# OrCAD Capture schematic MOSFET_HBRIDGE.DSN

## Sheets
1 PAGE2: size A
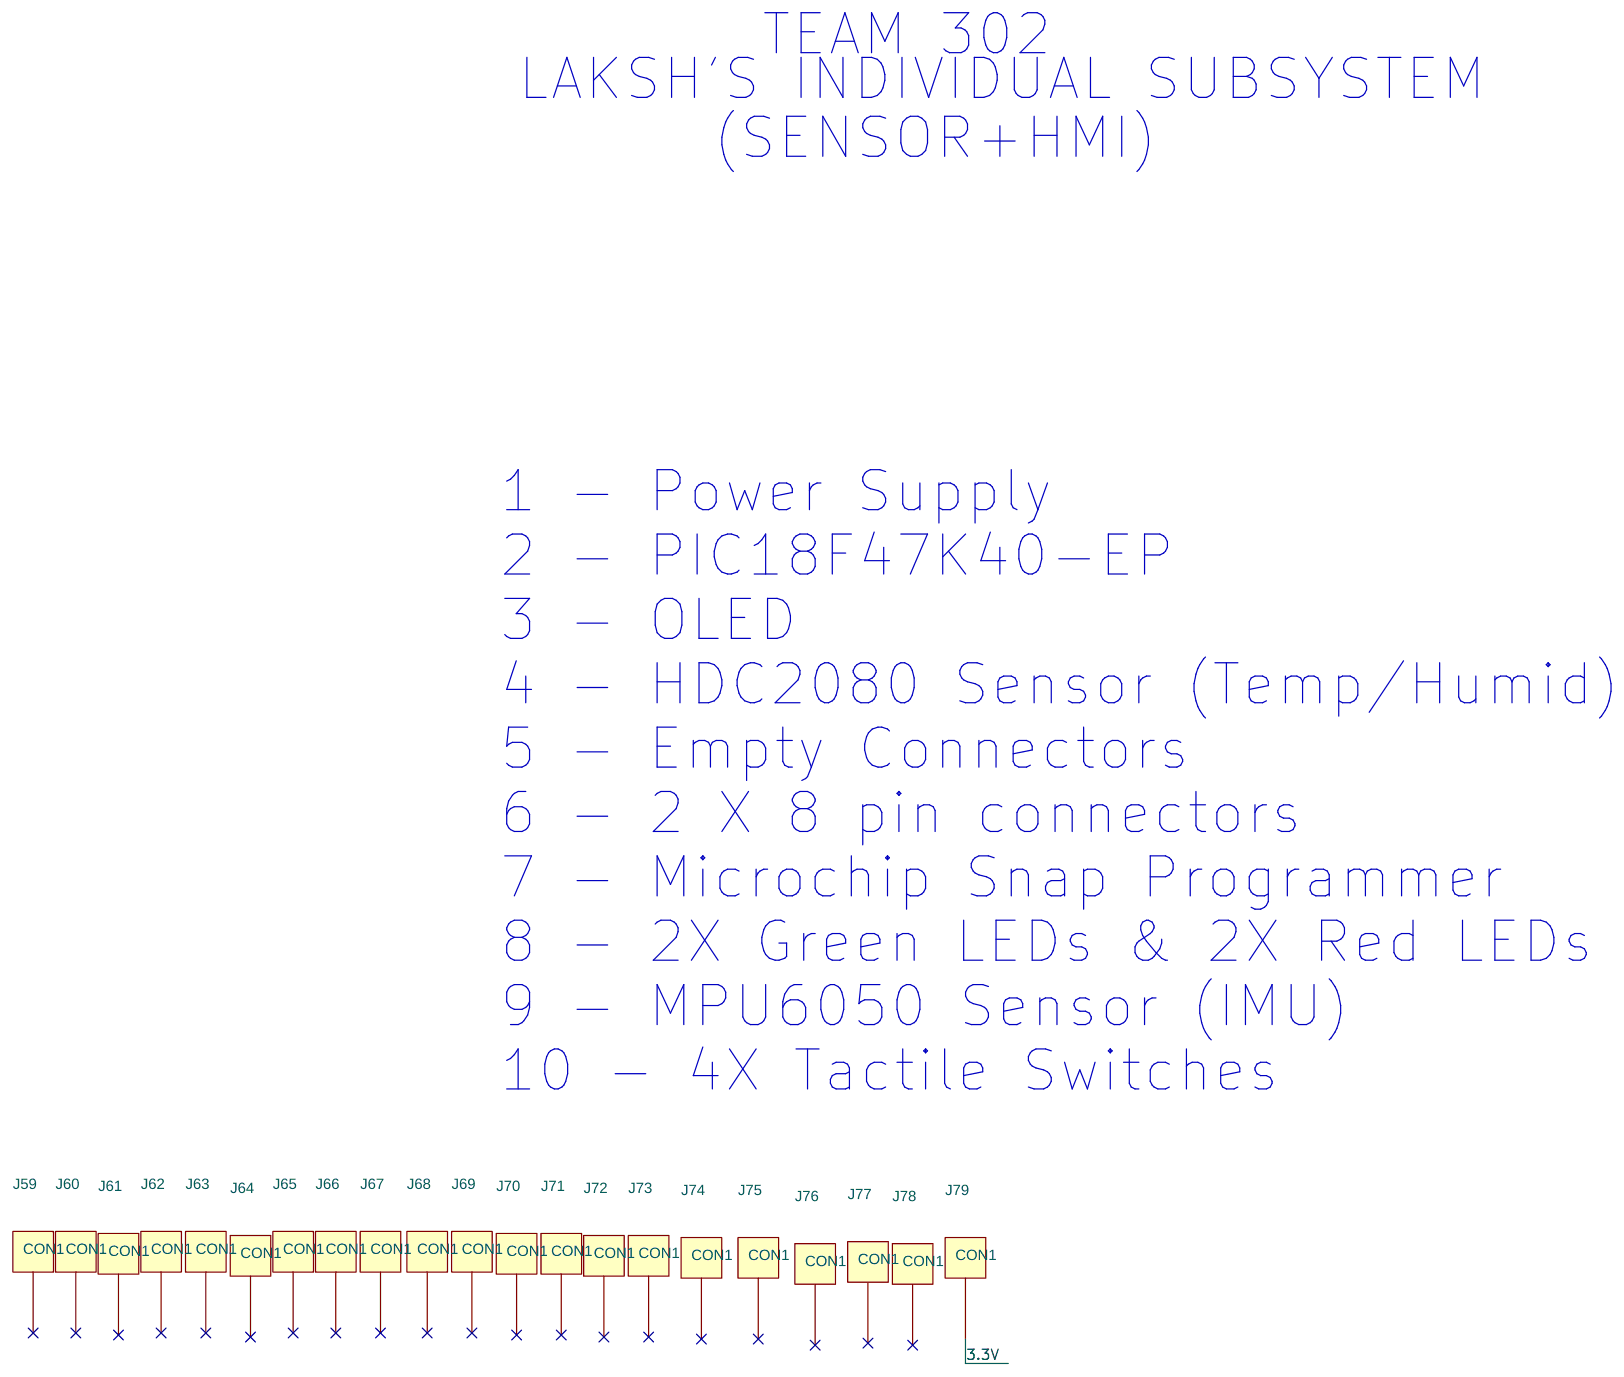
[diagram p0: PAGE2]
2 PAGE1: size A
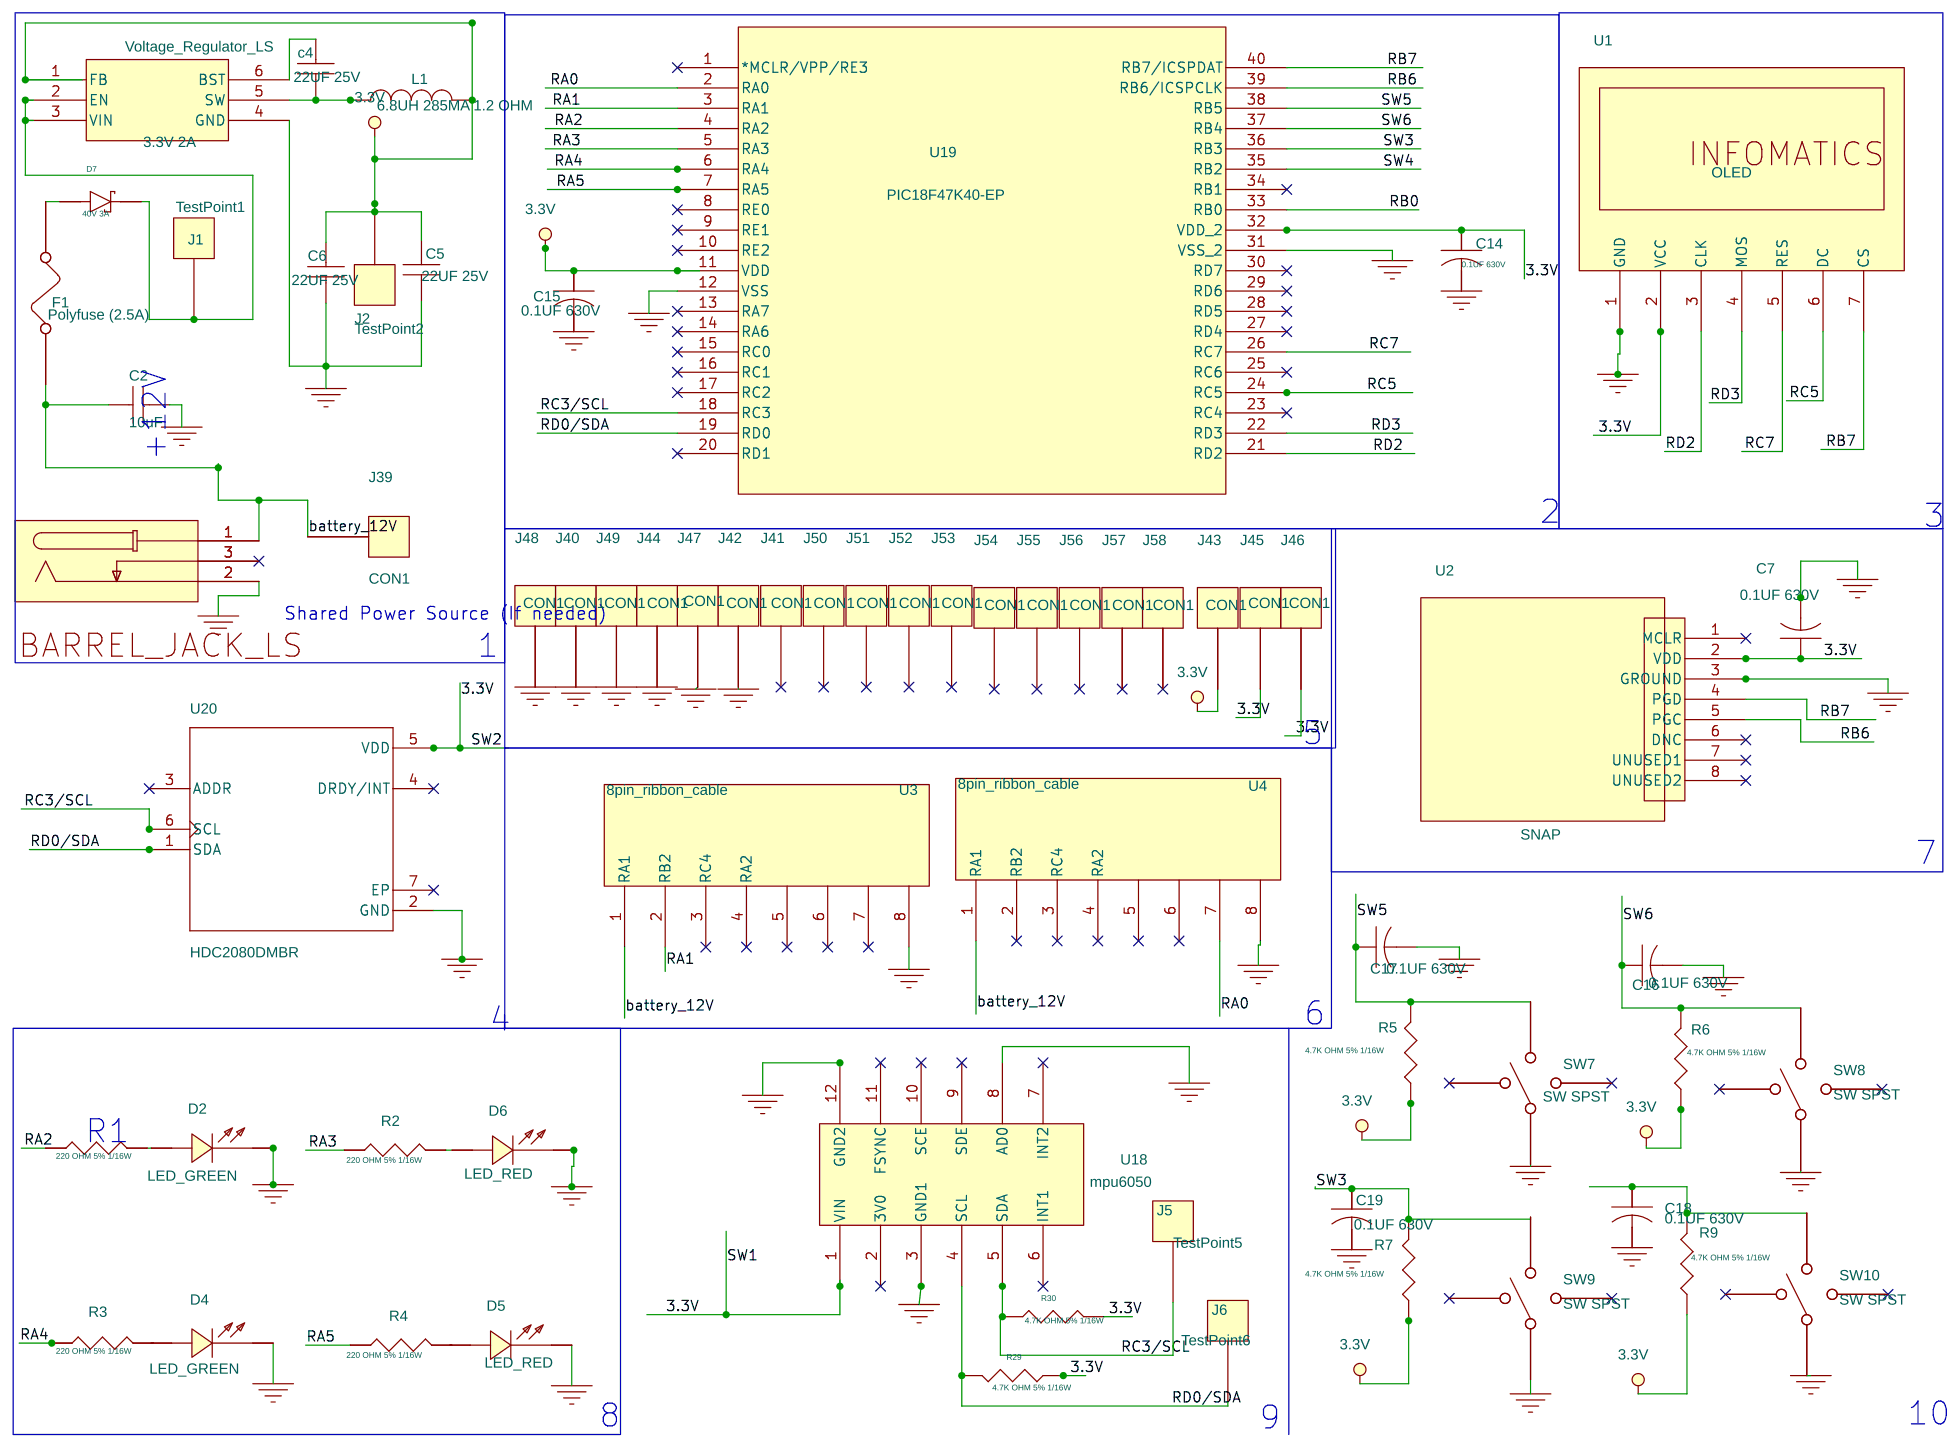
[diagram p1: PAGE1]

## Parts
sheet PAGE1
C2  10uF  [C4532_Commercial]
c4  22UF 25V  [C4532_Commercial]
C5  22UF 25V  [C4532_Commercial]
C6  22UF 25V  [C4532_Commercial]
C7  0.1UF 630V  [C4532_Commercial]
C14  0.1UF 630V  [C4532_Commercial]
C15  0.1UF 630V  [C4532_Commercial]
C16  0.1UF 630V  [C4532_Commercial]
C17  0.1UF 630V  [C4532_Commercial]
C18  0.1UF 630V  [C4532_Commercial]
C19  0.1UF 630V  [C4532_Commercial]
D2  LED_GREEN  [LED_LTST-C170GKT]
D4  LED_GREEN  [LED_LTST-C170GKT]
D5  LED_RED  [LED_LTST-C170GKT]
D6  LED_RED  [LED_LTST-C170GKT]
D7  40V 3A  [DIOM7959X261N]
F1  Polyfuse (2.5A)  [FUSE_01550900M_LTF]
J1  TestPoint1  [testpointconnectors]
J2  TestPoint2  [testpointconnectors]
J5  TestPoint5  [testpointconnectors]
J6  TestPoint6  [testpointconnectors]
J38  B_JACK  [NEB21R_LMB]
J39  CON1  [testpointconnectors]
J40  CON1  [testpointconnectors]
J41  CON1  [testpointconnectors]
J42  CON1  [testpointconnectors]
J43  CON1  [testpointconnectors]
J44  CON1  [testpointconnectors]
J45  CON1  [testpointconnectors]
J46  CON1  [testpointconnectors]
J47  CON1  [testpointconnectors]
J48  CON1  [testpointconnectors]
J49  CON1  [testpointconnectors]
J50  CON1  [testpointconnectors]
J51  CON1  [testpointconnectors]
J52  CON1  [testpointconnectors]
J53  CON1  [testpointconnectors]
J54  CON1  [testpointconnectors]
J55  CON1  [testpointconnectors]
J56  CON1  [testpointconnectors]
J57  CON1  [testpointconnectors]
J58  CON1  [testpointconnectors]
L1  6.8UH 285MA 1.2 OHM  [IND_PM1812]
R2  220 OHM 5% 1/16W  [RESC1005X40N]
R3  220 OHM 5% 1/16W  [RESC1005X40N]
R4  220 OHM 5% 1/16W  [RESC1005X40N]
R5  4.7K OHM 5% 1/16W  [RESC1005X40N]
R6  4.7K OHM 5% 1/16W  [RESC1005X40N]
R7  4.7K OHM 5% 1/16W  [RESC1005X40N]
R9  4.7K OHM 5% 1/16W  [RESC1005X40N]
R29  4.7K OHM 5% 1/16W  [RESC1005X40N]
R30  4.7K OHM 5% 1/16W  [RESC1005X40N]
RF0  220 OHM 5% 1/16W  [RESC1005X40N]
SW7  SW SPST  [SON4_PTS526SM15SMTR2LFS_CNK]
SW8  SW SPST  [SON4_PTS526SM15SMTR2LFS_CNK]
SW9  SW SPST  [SON4_PTS526SM15SMTR2LFS_CNK]
SW10  SW SPST  [SON4_PTS526SM15SMTR2LFS_CNK]
U1  OLED  [SH1106]
U2  SNAP  [8pincon]
U3  8pin_ribbon_cable  [8pincon]
U4  8pin_ribbon_cable  [8pincon]
U18  mpu6050  [mpu60509dof]
U19  PIC18F47K40-EP  [PDIP40_600MIL_P_MCH]
U20  HDC2080DMBR  [SON100P300X300X80-7N]
Voltage_Regulator_LS  3.3V 2A  [AP63203WU-7_DIO]
sheet PAGE2
J59  CON1  [testpointconnectors]
J60  CON1  [testpointconnectors]
J61  CON1  [testpointconnectors]
J62  CON1  [testpointconnectors]
J63  CON1  [testpointconnectors]
J64  CON1  [testpointconnectors]
J65  CON1  [testpointconnectors]
J66  CON1  [testpointconnectors]
J67  CON1  [testpointconnectors]
J68  CON1  [testpointconnectors]
J69  CON1  [testpointconnectors]
J70  CON1  [testpointconnectors]
J71  CON1  [testpointconnectors]
J72  CON1  [testpointconnectors]
J73  CON1  [testpointconnectors]
J74  CON1  [testpointconnectors]
J75  CON1  [testpointconnectors]
J76  CON1  [testpointconnectors]
J77  CON1  [testpointconnectors]
J78  CON1  [testpointconnectors]
J79  CON1  [testpointconnectors]

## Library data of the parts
C2 c4 C5 C6 = CAP_NP
C7 = CAPACITOR
C14-C19 = CAP
D2 D4-D6 = LED
D7 = MBRS340T3G
F1 = FUSE_SM
J1 J2 J5 J6 J39-J79 = CON1
J38 = B_JACK_8
L1 = INDUCTOR
R2-R7 R9 R29 R30 RF0 = RESISTOR
SW7-SW10 = SW_SPST_1
U1 = OLED
U2 = Snap_1
U3 U4 = 8pin_ribbon_cable
U18 = imu_1
U19 = PIC18F47K40-EP
U20 = HDC2080DMBR
Voltage_Regulator_LS = VR_LS_13

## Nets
3.3V: C5.1 C6.1 C7.1 C14.1 C15.1 J2.1 J43.1 J45.1 J46.1 L1.2 R5.1 R6.1 R7.1 R9.1 R29.1 R30.2 U1.2(VCC) U2.2(VDD) U18.1(VIN) U19.11(VDD) U19.32(VDD_2) U20.5(VDD) Voltage_Regulator_LS.1(FB)
3.3V (page PAGE2): J79.1
GND: C2.2 C5.2 C6.2 C7.2 C14.2 C15.2 C16.2 C17.2 C18.2 C19.2 D2.1(CATHODE) D4.1(CATHODE) D5.1(CATHODE) D6.1(CATHODE) J38.2 J40.1 J42.1 J44.1 J47.1 J48.1 J49.1 SW7.1 SW8.1 SW9.1 SW10.1 U1.1(GND) U2.3(GROUND) U3.8 U4.8 U18.3(GND1) U18.8(AD0) U18.12(GND2) U19.12(VSS) U19.31(VSS_2) U20.2(GND) Voltage_Regulator_LS.4(GND)
battery_12V: C2.1 F1.1 J38.1 J39.1 U3.1(RA1) U4.1(RA1)
RA0: U4.7 U19.2(RA0)
RA1: U3.2(RB2) U19.3(RA1)
RA2: RF0.1 U19.4(RA2)
RA3: R2.1 U19.5(RA3)
RA4: R3.1 U19.6(RA4)
RA5: R4.1 U19.7(RA5)
RB0: U19.33(RB0)
RB6: U2.5(PGC) U19.39(RB6/ICSPCLK)
RB7: U1.7(CS) U2.4(PGD) U19.40(RB7/ICSPDAT)
RC3/SCL: J5.1 R30.1 U18.5(SDA) U19.18(RC3) U20.6(SCL)
RC5: U1.6(DC) U19.24(RC5)
RC7: U1.5(RES) U19.26(RC7)
RD0/SDA: J6.1 R29.2 U18.4(SCL) U19.19(RD0) U20.1(SDA)
RD2: U1.3(CLK) U19.21(RD2)
RD3: U1.4(MOS) U19.22(RD3)
SW3: C19.1 R7.2 SW9.3 U19.36(RB3)
SW4: U19.35(RB2)
SW5: C17.1 R5.2 SW7.3 U19.38(RB5)
SW6: C16.1 R6.2 SW8.3 U19.37(RB4)
N134000: D7.C(K) J1.1 Voltage_Regulator_LS.2(EN) Voltage_Regulator_LS.3(VIN)
N134858: D2.2(ANODE) RF0.2
N146446: C18.1 R9.2 SW10.3
N147515: D6.2(ANODE) R2.2
N173405: c4.1 Voltage_Regulator_LS.6(BST)
N173558: c4.2 L1.1 Voltage_Regulator_LS.5(SW)
N176386: D7.A F1.2
N207613: D5.2(ANODE) R4.2
N207615: D4.2(ANODE) R3.2

Not connected (* = marked no-connect by the designer): J38 3*; J41 1*; J50 1*; J51 1*; J52 1*; J53 1*; J54 1*; J55 1*; J56 1*; J57 1*; J58 1*; J59 1*; J60 1*; J61 1*; J62 1*; J63 1*; J64 1*; J65 1*; J66 1*; J67 1*; J68 1*; J69 1*; J70 1*; J71 1*; J72 1*; J73 1*; J74 1*; J75 1*; J76 1*; J77 1*; J78 1*; SW7 2* 4*; SW8 2* 4*; SW9 2* 4*; SW10 2* 4*; U2 1(MCLR)* 6(DNC)* 7(UNUSED1)* 8(UNUSED2)*; U3 3(RC4)* 4(RA2)* 5* 6* 7*; U4 2(RB2)* 3(RC4)* 4(RA2)* 5* 6*; U18 2(3V0)* 6(INT1)* 7(INT2)* 9(SDE)* 10(SCE)* 11(FSYNC)*; U19 1(*MCLR/VPP/RE3)* 8(RE0)* 9(RE1)* 10(RE2)* 13(RA7)* 14(RA6)* 15(RC0)* 16(RC1)* 17(RC2)* 20(RD1)* 23(RC4)* 25(RC6)* 27(RD4)* 28(RD5)* 29(RD6)* 30(RD7)* 34(RB1)*; U20 3(ADDR)* 4(DRDY/INT)* 7(EP)*

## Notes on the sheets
sheet 1
- TEAM 302
- LAKSH'S INDIVIDUAL SUBSYSTEM
- (SENSOR+HMI)
- 1 - Power Supply
  2 - PIC18F47K40-EP
  3 - OLED
  4 - HDC2080 Sensor (Temp/Humid)
  5 - Empty Connectors
  6 - 2 X 8 pin connectors
  7 - Microchip Snap Programmer
  8 - 2X Green LEDs & 2X Red LEDs
  9 - MPU6050 Sensor (IMU)
  10 - 4X Tactile Switches
sheet 2
- +12V
- 2
- 3
- Shared Power Source (If needed)
- 1
- 5
- 7
- 6
- 4
- R1
- 8
- 9
- 10
